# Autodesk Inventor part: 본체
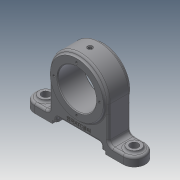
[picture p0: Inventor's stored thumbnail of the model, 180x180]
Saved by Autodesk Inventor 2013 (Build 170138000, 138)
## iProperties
Created: 2019-05
Part Number: 본체
Material: Generic
Document SubType Name: Modeling
Designer: user
Density: 1 g/cm^3
Author: user
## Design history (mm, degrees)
sketch "스케치1"
  geometry: C1 r 40 at (0, 0); 1 further point
  constraints: 1 centre point, 1 coincident
  dimensions: "d0" = 80 diameter of C1
extrude "돌출1" new body sketch "스케치1" stored distance "d1" = 30; taper "d2" = 0 deg
sketch "스케치2"
  geometry: C1 r 40 at (0, 0) reference; C2 r 36 at (0, 0)
  constraints: 1 centre point, 1 coincident
  dimensions: "d3" = 72 diameter of C2
extrude "돌출2" join sketch "스케치2" distance "d4" = 3; taper "d5" = 0 deg
sketch "스케치3"
  geometry: C1 r 36 at (0, 0) reference; C2 r 26 at (0, 0)
  constraints: 1 centre point, 1 coincident
  dimensions: "d6" = 52 diameter of C2
extrude "돌출3" cut sketch "스케치3" stored distance "d7" = 3; taper "d8" = 0 deg
node "작업 평면1"
sketch "스케치4"
  geometry: L1 (75, -15)-(-75, -15); L2 (-75, -15)-(-75, 15); L3 (-75, 15)-(75, 15); L4 (75, 15)-(75, -15); L5 (75, -15)-(-75, 15); L6 (-75, -15)-(75, 15); 1 further point
  constraints: 12 end point, 2 midpoint, 2 parallel, 1 horizontal, 1 perpendicular
  dimensions: "d10" = 150 distance of L2.end L3.end; "d11" = 30 distance of L1.end L2.end
extrude "돌출4" join sketch "스케치4" distance "d12" = 12; taper "d13" = 0 deg
sketch "스케치5"
  geometry: L1 (-40, 15)-(40, 15); L2 (40, 15)-(40, -15); L3 (40, -15)-(-40, -15); L4 (-40, -15)-(-40, 15); L5 (-40, 15)-(40, -15); L6 (40, 15)-(-40, -15); 1 further point
  constraints: 12 end point, 2 midpoint, 2 parallel, 1 horizontal, 1 perpendicular
  dimensions: "d14" = 80 distance of L2.end L3.end; "d15" = 30 distance of L1.end L2.end
extrude "돌출5" join sketch "스케치5" stored distance "d16" = 12; taper "d17" = 0 deg
sketch "스케치6"
  geometry: L1 (75, -60)-(-75, -60) reference; L2 (-36, -60)-(36, -60); L3 (36, -60)-(36, -56); L4 (36, -56)-(-36, -56); L5 (-36, -56)-(-36, -60); C1 r 36 at (0, 0) reference; 1 further point
  constraints: 8 end point, 2 parallel, 2 point on line, 1 midpoint, 1 perpendicular, 1 vertical alignment
  dimensions: "d18" = 72 distance of L2.start L2.end; "d19" = 4 distance of L3.end L2.end
extrude "돌출6" cut sketch "스케치6" stored distance "d20" = 12; taper "d21" = 0 deg
sketch "스케치7"
  geometry: L1 (-36, -56)-(36, -56) reference; L2 (-30, -56)-(30, -56); L3 (30, -56)-(30, -50); L4 (30, -50)-(-30, -50); L5 (-30, -50)-(-30, -56); A1 r 40 centre (0, 0) between (40, 0) and (-40, 0) reference; 1 further point
  constraints: 8 end point, 2 parallel, 2 point on line, 1 midpoint, 1 perpendicular, 1 vertical alignment
  dimensions: "d22" = 60 distance of L2.start L2.end; "d23" = 6 distance of L3.end L2.end
extrude "돌출7" cut sketch "스케치7" stored distance "d24" = 12; taper "d25" = 0 deg
sketch "스케치8"
  geometry: L1 (0, 0)-(0, 31); C1 r 36 at (0, 0) reference; 1 further point
  constraints: 2 end point, 1 coincident, 1 vertical
  dimensions: "d26" = 31 distance of L1.start L1.end
hole "구멍1" sketch "스케치8" at (0, 31) diameter "d27" = 3.242; stored, may be unused: countersink angle "d31" = 90 deg, drill point angle "d33" = 118 deg; dims "d28" = 6, "d29" = 4, "d30" = 2, "d32" = 8
sketch "스케치9"
  geometry: C1 r 26 at (0, 0) reference; C2 r 1.5 at (0, 26)
  constraints: 1 centre point, 1 vertical alignment
  dimensions: "d37" = 3 diameter of C2; "d38" = 26 distance of C1.centre C2.centre
extrude "돌출8" cut sketch "스케치9" stored distance "d39" = 12; taper "d40" = 0 deg
node "작업 평면2"
sketch "스케치10"
  geometry: 2 further points
  constraints: 1 coincident
hole "구멍2" sketch "스케치10" at (0, 0) diameter "d42" = 2; stored, may be unused: countersink angle "d46" = 90 deg, drill point angle "d48" = 118 deg; dims "d43" = 6, "d44" = 4, "d45" = 2, "d47" = 8
sketch "스케치11"
  geometry: 3 further points
  constraints: 2 coincident
hole "구멍3" sketch "스케치11" at (0, 0) diameter "d49" = 4.917; stored, may be unused: countersink angle "d53" = 90 deg, drill point angle "d55" = 118 deg; dims "d50" = 8, "d51" = 4, "d52" = 2, "d54" = 10
sketch "스케치12"
  geometry: C1 r 3.5 at (0, 0); 1 further point
  constraints: 1 centre point, 1 coincident
  dimensions: "d56" = 7 diameter of C1
extrude "돌출9" cut sketch "스케치12" distance "d57" = 1; taper "d58" = 0 deg
sketch "스케치13"
  geometry: C1 r 9 at (-60, 0); 1 further point
  constraints: 1 centre point, 1 horizontal alignment
  dimensions: "d59" = 18 diameter of C1; "d60" = 60 distance of C1.centre point (0, 0)
extrude "돌출10" join sketch "스케치13" distance "d61" = 3; taper "d62" = 0 deg
sketch "스케치14"
  geometry: C1 r 9 at (0, 0) reference; C2 r 5.5 at (0, 0); 1 further point
  constraints: 1 centre point, 1 coincident
  dimensions: "d63" = 11 diameter of C2
extrude "돌출11" cut sketch "스케치14" stored distance "d64" = 3; taper "d65" = 0 deg
fillet "모깎기1" dims "d66" = 6
fillet "모깎기2" dims "d67" = 3
fillet "모깎기3" dims "d68" = 3
fillet "모깎기4" dims "d69" = 15
fillet "모깎기5" dims "d70" = 15
fillet "모깎기6" dims "d71" = 3
fillet "모깎기7" dims "d72" = 3
fillet "모깎기8" dims "d73" = 3
sketch "스케치15"
  geometry: L1 (-27, -50)-(27, -50) reference; A1 r 39 centre (0, 0) between (-37, -12.329) and (37, -12.329) reference; 1 further point
  constraints: 1 vertical alignment, 1 other
  dimensions: "d75" = 7 distance from line of L1 point (0, -43)
feature "엠보싱1" sketch "스케치15" dims "d0" = 80, "d76" = 0.5, "d77" = 0
fillet "모깎기9" dims "d78" = 3
chamfer "모따기1" distance "d79" = 1; stored, may be unused: second distance "d80" = 2, angle "d81" = 45 deg
node "솔리드1"
mirror "대칭1"
pattern_circular "원형 패턴1" dims angle "d35" = 360 deg
mirror "대칭2"
mirror "대칭3"
